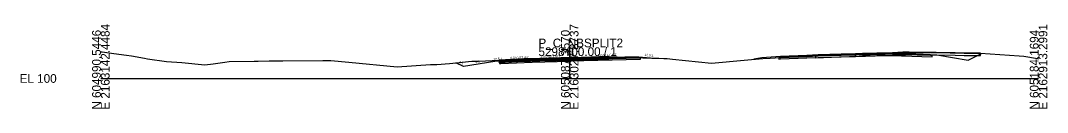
# Model space of a CAD drawing. Extents: x -26 to 1303, y -10 to 12038.
# Drawn here: x -25.7 to 302.8, y 9490.3 to 9517.4 of the extents above; entities that cross this region are included whole.
import ezdxf

# ---------------------------------------------------------------- set-up
doc = ezdxf.new("R2010")
doc.units = 0
for name, color, linetype in [('RD_GPK_XS_Cell', 7, 'Continuous'), ('RD_XS_Base', 7, 'Continuous'), ('RD_XS_ExGround', 7, 'Continuous'), ('RD_XS_ExPaveRet', 7, 'Continuous'), ('RD_XS_Greenside', 7, 'Continuous'), ('RD_XS_Pave', 7, 'Continuous'), ('RD_XS_PaveOvlay_CP', 7, 'Continuous'), ('RD_XS_TieSlope', 7, 'Continuous'), ('RD_XS_TX_Elev_EX', 7, 'Continuous'), ('RD_XS_TX_Elev_PR', 7, 'Continuous'), ('RD_XS_TX_ShdSlope', 7, 'Continuous'), ('RD_XS_TX_Slope', 7, 'Continuous')]:
    doc.layers.add(name, color=color, linetype=linetype)

msp = doc.modelspace()

# ---------------------------------------------------------------- linework, layer by layer
at = {"layer": 'RD_GPK_XS_Cell'}
for p, q in [((150, 9500), (150, 9510)), ((0, 9500), (150, 9500)), ((150, 9500), (300, 9500))]:
    msp.add_line(p, q, dxfattribs=at)
at = {"layer": 'RD_XS_Base'}
for p, q in [((250.97, 9507.83), (241.45, 9507.57)), ((253.45, 9507.9), (250.97, 9507.83)), ((256, 9507.8), (253.45, 9507.9)), ((265.45, 9507.43), (256, 9507.8)), ((128, 9505.33), (127.5, 9505.31)), ((127.5, 9505.31), (127.5, 9505.31)), ((127.5, 9505.31), (127.5, 9504.81)), ((127.5, 9504.81), (128, 9504.83)), ((138, 9505.73), (128, 9505.33)), ((128, 9505.33), (128, 9505.33)), ((128, 9504.83), (138, 9505.23)), ((128, 9504.83), (128, 9504.83)), ((150, 9506.04), (138, 9505.73)), ((138, 9505.73), (138, 9505.73)), ((138, 9505.23), (150, 9505.54)), ((138, 9505.23), (138, 9505.23)), ((150, 9506.04), (172.5, 9506.62)), ((150, 9505.54), (150, 9506.2)), ((150, 9506.2), (150, 9506.2)), ((150, 9506.2), (150, 9506.2)), ((150, 9506.2), (150, 9506.04)), ((172.5, 9506.12), (150, 9505.54)), ((150, 9506.04), (150, 9506.04)), ((150, 9505.54), (150, 9506.04)), ((150, 9506.04), (150, 9506.04)), ((150, 9506.04), (150, 9506.04)), ((150, 9505.54), (150, 9505.54)), ((172, 9506.61), (172, 9506.61)), ((172, 9506.61), (172, 9506.61)), ((172, 9506.61), (172, 9506.61)), ((172, 9506.11), (172, 9506.11)), ((172, 9506.11), (172, 9506.11)), ((172.5, 9506.62), (172.5, 9506.12)), ((172.5, 9506.59), (172.5, 9506.59)), ((217.37, 9506.75), (216.95, 9506.73)), ((216.95, 9506.73), (216.95, 9506.65)), ((216.95, 9506.65), (216.95, 9506.23)), ((216.95, 9506.23), (217.37, 9506.25)), ((217.45, 9506.75), (217.37, 9506.75)), ((217.37, 9506.25), (217.45, 9506.25)), ((225.81, 9507.09), (217.45, 9506.75)), ((217.45, 9506.25), (225.81, 9506.59)), ((229.45, 9507.23), (225.81, 9507.09)), ((225.81, 9506.59), (229.45, 9506.73)), ((236.89, 9507.44), (229.45, 9507.23)), ((229.45, 9506.73), (236.89, 9506.94)), ((241.45, 9507.57), (236.89, 9507.44)), ((236.89, 9506.94), (241.45, 9507.07)), ((241.45, 9507.7), (241.45, 9507.73)), ((241.45, 9507.73), (241.45, 9507.6)), ((241.45, 9507.57), (241.45, 9507.7)), ((241.45, 9507.6), (241.45, 9507.07)), ((241.45, 9507.57), (241.45, 9507.57)), ((241.45, 9507.57), (241.45, 9507.57)), ((241.45, 9507.47), (241.45, 9507.57)), ((241.45, 9507.07), (241.45, 9507.47)), ((241.45, 9507.07), (250.97, 9507.33)), ((250.97, 9507.33), (253.45, 9507.4)), ((253.45, 9507.4), (256.11, 9507.3)), ((256.11, 9507.3), (265.95, 9506.91)), ((265.56, 9507.42), (265.45, 9507.43)), ((265.95, 9507.41), (265.56, 9507.42)), ((265.95, 9507.29), (265.95, 9507.41)), ((265.95, 9506.91), (265.95, 9507.29))]:
    msp.add_line(p, q, dxfattribs=at)
at = {"layer": 'RD_XS_ExGround'}
msp.add_lwpolyline([(0, 9508.56), (0.47, 9508.5), (4.16, 9508), (8.18, 9507.5), (9.76, 9507.26), (13.96, 9506.49), (14.93, 9506.31), (20.99, 9505.48), (25.93, 9505.09), (33.28, 9504.35), (35.95, 9504.7), (39.67, 9505.19), (41.1, 9505.4), (49.1, 9505.57), (49.65, 9505.58), (50.3, 9505.6), (53.84, 9505.69), (58.24, 9505.69), (71.02, 9505.72), (72.85, 9505.75), (73.55, 9505.77), (79.34, 9505.18), (94.75, 9503.76), (105.42, 9504.44), (106.25, 9504.5), (106.9, 9504.5), (107.48, 9504.5), (111.49, 9504.85), (118.71, 9505.5), (120.8, 9505.59), (127.43, 9505.88), (135.35, 9506.28), (136.11, 9506.31), (137.44, 9506.35), (143.46, 9506.5), (144.41, 9506.5), (145.76, 9506.5), (145.81, 9506.51), (147.15, 9506.61), (150.56, 9506.66), (156.72, 9506.85), (162.47, 9507.03), (170.45, 9506.76), (176.26, 9506.55), (177.46, 9506.5), (178.54, 9506.47), (180.16, 9506.43), (181.15, 9506.4), (182.87, 9506.19), (195.39, 9504.88), (205.79, 9505.88), (211.81, 9506.42), (214.18, 9506.5), (227.17, 9507.32), (228.65, 9507.42), (242.55, 9507.94), (244.08, 9507.99), (245.32, 9508.03), (248.29, 9508.13), (256.53, 9508.39), (258.63, 9508.4), (265.68, 9508.34), (267.22, 9508.32), (276.24, 9508.17), (281.4, 9508.07), (293.81, 9507.3), (295.31, 9507.2), (299.68, 9506.36), (300, 9506.31)], dxfattribs=at)
at = {"layer": 'RD_XS_ExPaveRet'}
for points in [[(281.4, 9508.07), (281.4, 9508.07), (278.39, 9508.13), (276.24, 9508.17), (273.27, 9508.22), (267.25, 9508.32), (267.23, 9508.32), (267.22, 9508.32), (267.2, 9508.32), (265.64, 9508.34), (261.12, 9508.38), (258.63, 9508.4), (257.44, 9508.39), (256.53, 9508.39), (253.29, 9508.28), (248.29, 9508.13), (246.23, 9508.06), (245.32, 9508.03), (244.45, 9508), (244.08, 9507.99), (243.64, 9507.97), (242.55, 9507.94), (236.31, 9507.71), (228.65, 9507.42), (228.65, 9506.97), (228.65, 9506.67), (236.31, 9506.96), (242.55, 9507.19), (243.64, 9507.22), (244.08, 9507.24), (244.45, 9507.25), (245.32, 9507.28), (246.23, 9507.31), (248.29, 9507.38), (253.29, 9507.53), (256.53, 9507.64), (257.44, 9507.64), (258.63, 9507.65), (261.12, 9507.63), (265.64, 9507.59), (267.2, 9507.57), (267.22, 9507.57), (267.23, 9507.57), (267.25, 9507.57), (273.27, 9507.47), (276.24, 9507.42), (278.39, 9507.38), (281.4, 9507.32), (281.4, 9507.32), (281.4, 9507.32), (281.4, 9507.59), (281.4, 9508.07), (281.4, 9508.07)], [(281.4, 9508.07), (281.4, 9508.07), (278.39, 9508.13), (276.24, 9508.17), (273.27, 9508.22), (267.25, 9508.32), (267.23, 9508.32), (267.22, 9508.32), (267.2, 9508.32), (265.64, 9508.34), (261.12, 9508.38), (258.63, 9508.4), (257.44, 9508.39), (256.53, 9508.39), (253.29, 9508.28), (248.29, 9508.13), (246.23, 9508.06), (245.32, 9508.03), (244.45, 9508), (244.08, 9507.99), (243.64, 9507.97), (242.55, 9507.94), (236.31, 9507.71), (228.65, 9507.42), (228.65, 9506.97), (228.65, 9506.67), (236.31, 9506.96), (242.55, 9507.19), (243.64, 9507.22), (244.08, 9507.24), (244.45, 9507.25), (245.32, 9507.28), (246.23, 9507.31), (248.29, 9507.38), (253.29, 9507.53), (256.53, 9507.64), (257.44, 9507.64), (258.63, 9507.65), (261.12, 9507.63), (265.64, 9507.59), (267.2, 9507.57), (267.22, 9507.57), (267.23, 9507.57), (267.25, 9507.57), (273.27, 9507.47), (276.24, 9507.42), (278.39, 9507.38), (281.4, 9507.32), (281.4, 9507.32), (281.4, 9507.32), (281.4, 9507.59), (281.4, 9508.07), (281.4, 9508.07)], [(162.47, 9507.03), (162.47, 9507.03), (162.47, 9507.03), (162.47, 9506.28), (162.47, 9506.28), (156.72, 9506.1), (156.72, 9506.1), (150.56, 9505.91), (147.15, 9505.86), (147.15, 9505.86), (145.81, 9505.76), (145.81, 9505.76), (145.76, 9505.75), (145.76, 9505.75), (145.76, 9505.75), (144.41, 9505.75), (144.41, 9505.75), (143.46, 9505.75), (143.46, 9505.75), (137.44, 9505.6), (137.44, 9505.6), (136.11, 9505.56), (135.35, 9505.53), (135.35, 9505.53), (127.43, 9505.13), (127.43, 9505.13), (127.43, 9505.88), (127.43, 9505.88), (127.43, 9505.88), (135.35, 9506.28), (135.35, 9506.28), (136.11, 9506.31), (137.44, 9506.35), (137.44, 9506.35), (143.46, 9506.5), (143.46, 9506.5), (144.41, 9506.5), (144.41, 9506.5), (145.76, 9506.5), (145.76, 9506.5), (145.76, 9506.5), (145.81, 9506.51), (145.81, 9506.51), (147.15, 9506.61), (147.15, 9506.61), (150.56, 9506.66), (156.72, 9506.85), (156.72, 9506.85), (162.47, 9507.03)], [(156.72, 9506.85), (150.56, 9506.66), (147.15, 9506.61), (145.81, 9506.51), (145.76, 9506.5), (144.41, 9506.5), (143.46, 9506.5), (137.44, 9506.35), (136.11, 9506.31), (135.35, 9506.28), (127.43, 9505.88), (127.43, 9505.13), (135.35, 9505.53), (136.11, 9505.56), (137.44, 9505.6), (143.46, 9505.75), (144.41, 9505.75), (145.76, 9505.75), (145.81, 9505.76), (147.15, 9505.86), (150.56, 9505.91), (156.72, 9506.1), (162.47, 9506.28), (162.47, 9507.03), (156.72, 9506.85)]]:
    msp.add_lwpolyline(points, dxfattribs=at)
at = {"layer": 'RD_XS_Greenside'}
for p, q in [((277.45, 9505.92), (281.72, 9508.05)), ((116, 9503.82), (113.56, 9505.03)), ((126, 9505.48), (116, 9503.82)), ((211.45, 9506.59), (208.87, 9506.16)), ((267.45, 9507.58), (277.45, 9505.92))]:
    msp.add_line(p, q, dxfattribs=at)
at = {"layer": 'RD_XS_Pave'}
for p, q in [((236.89, 9507.76), (229.45, 9507.55)), ((241.45, 9507.89), (236.89, 9507.76)), ((250.97, 9508.15), (241.45, 9507.89)), ((250.97, 9507.99), (241.45, 9507.73)), ((241.45, 9507.73), (250.97, 9507.99)), ((241.45, 9507.57), (250.97, 9507.83)), ((253.45, 9508.22), (250.97, 9508.15)), ((253.45, 9508.06), (250.97, 9507.99)), ((250.97, 9507.99), (253.45, 9508.06)), ((250.97, 9507.83), (253.45, 9507.9)), ((256, 9508.12), (253.45, 9508.22)), ((256, 9507.96), (253.45, 9508.06)), ((253.45, 9508.06), (256, 9507.96)), ((253.45, 9507.9), (256, 9507.8)), ((265.45, 9507.74), (256, 9508.12)), ((265.45, 9507.58), (256, 9507.96)), ((256, 9507.96), (265.45, 9507.58)), ((256, 9507.8), (265.45, 9507.43)), ((265.45, 9507.71), (265.45, 9507.74)), ((138, 9506.04), (128, 9505.64)), ((128, 9505.48), (138, 9505.88)), ((138, 9505.88), (128, 9505.48)), ((128, 9505.33), (138, 9505.73)), ((128, 9505.64), (128, 9505.64)), ((128, 9505.64), (128, 9505.48)), ((128, 9505.48), (128, 9505.48)), ((128, 9505.48), (128, 9505.33)), ((150, 9506.36), (138, 9506.04)), ((138, 9505.88), (150, 9506.2)), ((150, 9506.2), (138, 9505.88)), ((138, 9506.04), (138, 9506.04)), ((138, 9505.73), (150, 9506.04)), ((138, 9505.88), (138, 9505.88)), ((138, 9505.88), (138, 9505.88)), ((138, 9505.73), (138, 9505.73)), ((172, 9506.93), (150, 9506.36)), ((172, 9506.77), (150, 9506.2)), ((150, 9506.2), (172, 9506.77)), ((150, 9506.04), (172, 9506.61)), ((150, 9506.36), (150, 9506.36)), ((150, 9506.2), (150, 9506.2)), ((150, 9506.2), (150, 9506.2)), ((150, 9506.2), (150, 9506.04)), ((150, 9506.2), (150, 9506.2)), ((150, 9506.04), (150, 9506.2)), ((150, 9506.2), (150, 9506.2)), ((150, 9506.2), (150, 9506.2)), ((150, 9506.04), (150, 9506.04)), ((150, 9506.04), (150, 9506.04)), ((172, 9506.77), (172, 9506.93)), ((172, 9506.93), (172, 9506.93)), ((172, 9506.93), (172, 9506.93)), ((172, 9506.93), (172, 9506.93)), ((172, 9506.61), (172, 9506.77)), ((172, 9506.77), (172, 9506.77)), ((172, 9506.77), (172, 9506.77)), ((172, 9506.77), (172, 9506.77)), ((172, 9506.77), (172, 9506.77)), ((172, 9506.77), (172, 9506.77)), ((172, 9506.61), (172, 9506.61)), ((172, 9506.61), (172, 9506.61)), ((225.81, 9507.4), (217.45, 9507.07)), ((225.81, 9507.24), (217.45, 9506.91)), ((217.45, 9506.91), (225.81, 9507.24)), ((217.45, 9506.75), (225.81, 9507.09)), ((217.45, 9507.07), (217.45, 9507.04)), ((217.45, 9507.04), (217.45, 9506.91)), ((217.45, 9506.91), (217.45, 9506.89)), ((217.45, 9506.89), (217.45, 9506.75)), ((229.45, 9507.55), (225.81, 9507.4)), ((229.45, 9507.39), (225.81, 9507.24)), ((225.81, 9507.24), (229.45, 9507.39)), ((225.81, 9507.09), (229.45, 9507.23)), ((236.89, 9507.6), (229.45, 9507.39)), ((229.45, 9507.39), (236.89, 9507.6)), ((229.45, 9507.23), (236.89, 9507.44)), ((241.45, 9507.73), (236.89, 9507.6)), ((236.89, 9507.6), (241.45, 9507.73)), ((236.89, 9507.44), (241.45, 9507.57)), ((241.45, 9507.7), (241.45, 9507.73)), ((241.45, 9507.73), (241.45, 9507.73)), ((241.45, 9507.73), (241.45, 9507.73)), ((241.45, 9507.73), (241.45, 9507.7)), ((241.45, 9507.57), (241.45, 9507.7)), ((241.45, 9507.7), (241.45, 9507.57)), ((241.45, 9507.57), (241.45, 9507.57)), ((241.45, 9507.57), (241.45, 9507.57)), ((265.45, 9507.58), (265.45, 9507.71)), ((265.45, 9507.55), (265.45, 9507.58)), ((265.45, 9507.43), (265.45, 9507.55))]:
    msp.add_line(p, q, dxfattribs=at)
at = {"layer": 'RD_XS_PaveOvlay_CP'}
for p, q in [((236.89, 9507.76), (229.45, 9507.55)), ((241.45, 9507.89), (236.89, 9507.76)), ((250.97, 9508.15), (241.45, 9507.89)), ((253.45, 9508.22), (250.97, 9508.15)), ((256, 9508.12), (253.45, 9508.22)), ((265.45, 9507.74), (256, 9508.12)), ((138, 9506.04), (128, 9505.64)), ((150, 9506.36), (138, 9506.04)), ((138, 9506.04), (138, 9506.04)), ((172, 9506.93), (150, 9506.36)), ((150, 9506.36), (150, 9506.36)), ((172, 9506.93), (172, 9506.93)), ((172, 9506.93), (172, 9506.93)), ((225.81, 9507.4), (217.45, 9507.07)), ((229.45, 9507.55), (225.81, 9507.4))]:
    msp.add_line(p, q, dxfattribs=at)
at = {"layer": 'RD_XS_TieSlope'}
for p, q in [((265.45, 9507.74), (267.45, 9507.58)), ((128, 9505.64), (126, 9505.48)), ((172, 9506.93), (177.11, 9506.52)), ((217.45, 9507.07), (211.45, 9506.59))]:
    msp.add_line(p, q, dxfattribs=at)

# ---------------------------------------------------------------- texts
at = {"layer": 'RD_GPK_XS_Cell'}
for s, p in [('N 604990.5446', (0, 9490)), ('E 2163142.4484', (2.8, 9490)), ('N 605087.3570', (150, 9490)), ('E 2163027.8737', (152.8, 9490)), ('N 605184.1694', (300, 9490)), ('E 2162913.2991', (302.8, 9490))]:
    msp.add_text(s, height=2.8, rotation=90, dxfattribs=at).set_placement(p)
for s, p in [('P_C_NBSPLIT2', (140, 9510)), ('5298+00.00 / 1', (140, 9507.2)), ('EL 100', (-26, 9498.6))]:
    msp.add_text(s, height=2.8, dxfattribs=at).set_placement(p)
at = {"layer": 'RD_XS_TX_Elev_EX'}
msp.add_text('106.65', height=0.6, rotation=90, dxfattribs=at).set_placement((149.72, 9507.13))
at = {"layer": 'RD_XS_TX_Elev_PR'}
msp.add_text('106.36', height=1, rotation=90, dxfattribs=at).set_placement((151.32, 9506.75))
at = {"layer": 'RD_XS_TX_ShdSlope'}
for rotation, p in [(355.4261, (173.89, 9507.23)), (4.5739, (125.58, 9505.77))]:
    msp.add_text('12.5:1', height=0.75, rotation=rotation, dxfattribs=at).set_placement(p)
at = {"layer": 'RD_XS_TX_Slope'}
for s, rotation, p in [('0.028 FT./FT.', 1.6039, (159, 9507.05)), ('2:1', 333.4349, (114.49, 9505.05)), ('6:1', 9.4642, (119.89, 9504.9)), ('0.040 FT./FT.', 2.2906, (130.99, 9506.18)), ('0.028 FT./FT.', 1.6039, (141, 9506.55))]:
    msp.add_text(s, height=0.75, rotation=rotation, dxfattribs=at).set_placement(p)

doc.saveas('drawing.dxf')
